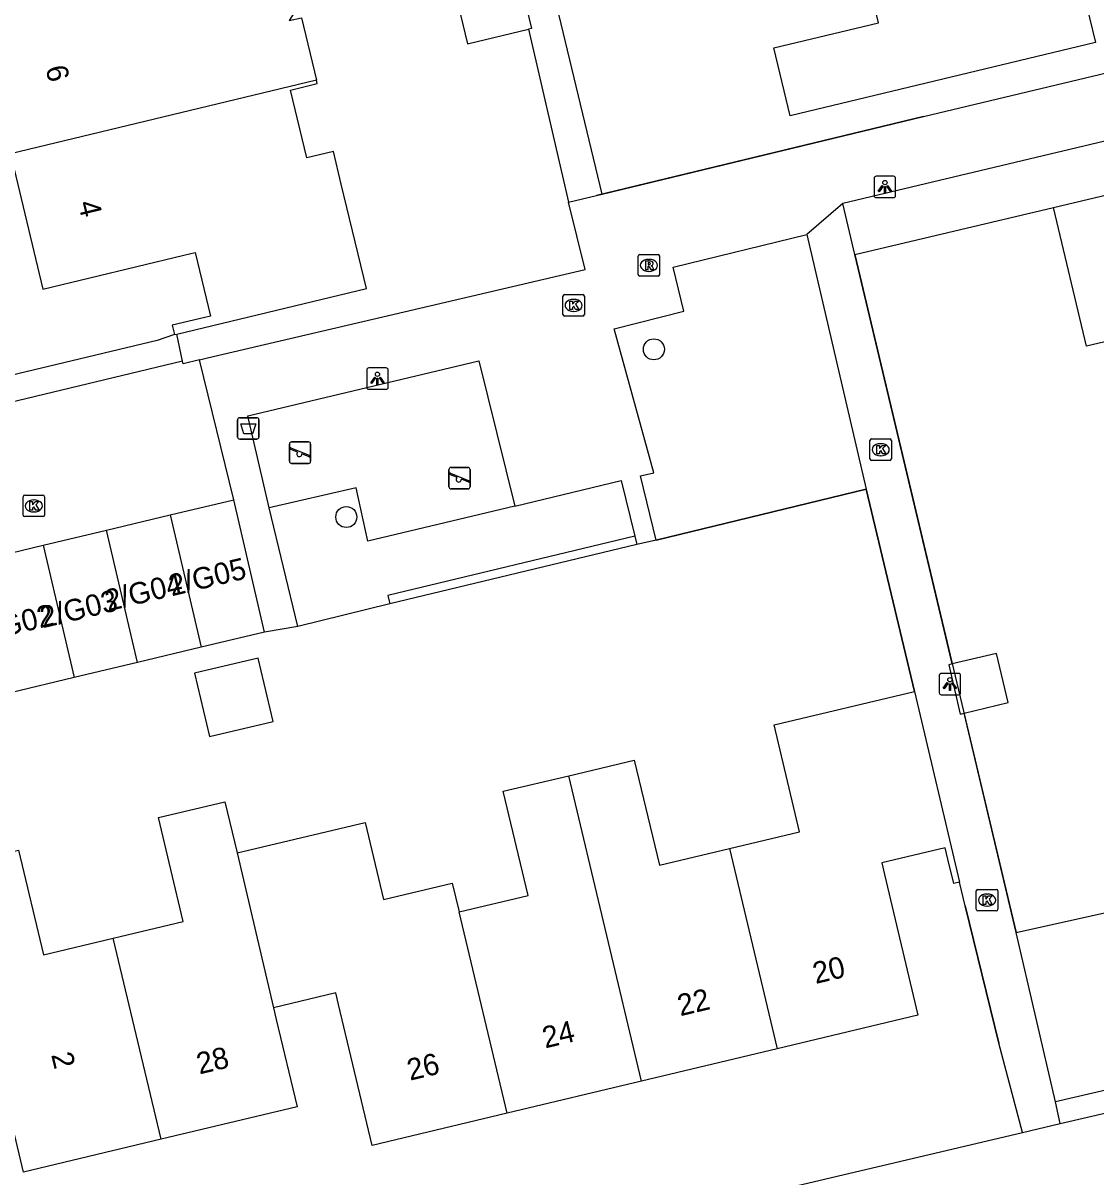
# Model space of a CAD drawing. Extents: x 157663 to 158496, y 379212 to 380934.
# Drawn here: x 158176.8 to 158226.7, y 380778.9 to 380832.6 of the extents above; entities that cross this region are included whole.
import ezdxf

# ---------------------------------------------------------------- set-up
doc = ezdxf.new("R2010")
doc.units = 0
for name, color, linetype in [('IMGEO_Afvalbak', 7, 'Continuous'), ('IMGEO_Boom', 7, 'Continuous'), ('IMGEO_Groenvoorziening', 7, 'Continuous'), ('IMGEO_Haag', 7, 'Continuous'), ('IMGEO_Hek', 7, 'Continuous'), ('IMGEO_Kolk', 7, 'Continuous'), ('IMGEO_Lichtpunt', 7, 'Continuous'), ('IMGEO_Pand', 7, 'Continuous'), ('IMGEO_Pand_nummerreeks', 7, 'Continuous'), ('IMGEO_Rijbaan_lokaal_open', 7, 'Continuous'), ('IMGEO_Rioolput', 7, 'Continuous'), ('IMGEO_Speelvoorziening', 7, 'Continuous'), ('IMGEO_Voetpad_open', 7, 'Continuous')]:
    doc.layers.add(name, color=color, linetype=linetype)

msp = doc.modelspace()

# ---------------------------------------------------------------- linework, layer by layer
at = {"layer": 'IMGEO_Afvalbak'}
for p, q in [((158186.742, 380813.303), (158186.742, 380814.103)), ((158186.742, 380814.103), (158186.742, 380813.303)), ((158186.842, 380814.203), (158187.632, 380814.203)), ((158187.632, 380814.203), (158186.842, 380814.203)), ((158187.732, 380814.103), (158187.732, 380813.303)), ((158187.732, 380813.303), (158187.732, 380814.103)), ((158187.632, 380813.203), (158186.842, 380813.203)), ((158186.842, 380813.203), (158187.632, 380813.203))]:
    msp.add_line(p, q, dxfattribs=at)
msp.add_lwpolyline([(158186.885, 380813.917), (158187.589, 380813.917), (158187.44, 380813.447), (158187.034, 380813.447), (158186.885, 380813.917)], dxfattribs=at)
for centre, start, end in [((158186.842, 380814.103), 90, 180), ((158186.842, 380814.103), 90, 180), ((158187.632, 380814.103), 0, 90), ((158187.632, 380814.103), 360, 90), ((158186.842, 380813.303), 180, 270), ((158186.842, 380813.303), 180, 270), ((158187.632, 380813.303), 270, 0), ((158187.632, 380813.303), 270, 0)]:
    msp.add_arc(centre, 0.1, start, end, dxfattribs=at)
at = {"layer": 'IMGEO_Boom'}
for centre in [(158206.111, 380817.384), (158191.799, 380809.579)]:
    msp.add_circle(centre, 0.489, dxfattribs=at)
at = {"layer": 'IMGEO_Groenvoorziening'}
for points in [[(158199.64, 380810.083), (158192.801, 380808.454), (158192.253, 380810.936), (158188.21, 380810.007)], [(158215.996, 380810.883), (158206.225, 380808.502)], [(158193.832, 380805.542), (158189.539, 380804.491)]]:
    msp.add_lwpolyline(points, dxfattribs=at)
at = {"layer": 'IMGEO_Haag'}
for points in [[(158205.233, 380808.682), (158193.739, 380805.931), (158193.832, 380805.542)], [(158205.326, 380808.293), (158193.832, 380805.542)]]:
    msp.add_lwpolyline(points, dxfattribs=at)
at = {"layer": 'IMGEO_Hek'}
for points in [[(158218.664, 380828.221), (158203.449, 380824.546)], [(158185.335, 380816.982), (158202.908, 380821.094), (158202.136, 380824.23)], [(158215.467, 380821.796), (158224.705, 380823.985)], [(158215.467, 380821.796), (158222.973, 380790.246)], [(158206.225, 380808.502), (158215.996, 380810.883)], [(158215.996, 380810.883), (158218.24, 380801.457)], [(158220.598, 380791.484), (158222.164, 380785.085)]]:
    msp.add_lwpolyline(points, dxfattribs=at)
at = {"layer": 'IMGEO_Kolk'}
for p, q in [((158201.951, 380819.93), (158202.803, 380819.93)), ((158201.876, 380819.004), (158201.876, 380819.856)), ((158202.364, 380819.71), (158202.389, 380819.71)), ((158202.877, 380819.856), (158202.877, 380819.004)), ((158202.803, 380818.93), (158201.951, 380818.93)), ((158202.387, 380819.15), (158202.362, 380819.15)), ((158216.166, 380812.287), (158216.166, 380813.139)), ((158216.241, 380813.213), (158217.093, 380813.213)), ((158216.654, 380812.993), (158216.679, 380812.993)), ((158217.167, 380813.139), (158217.167, 380812.287)), ((158216.677, 380812.433), (158216.652, 380812.433)), ((158217.093, 380812.213), (158216.241, 380812.213)), ((158176.758, 380809.67), (158176.758, 380810.522)), ((158176.833, 380810.596), (158177.685, 380810.596)), ((158177.246, 380810.376), (158177.271, 380810.376)), ((158177.759, 380810.522), (158177.759, 380809.67)), ((158177.269, 380809.816), (158177.244, 380809.816)), ((158177.685, 380809.596), (158176.833, 380809.596)), ((158221.116, 380791.324), (158221.116, 380792.176)), ((158221.191, 380792.25), (158222.043, 380792.25)), ((158221.604, 380792.03), (158221.629, 380792.03)), ((158222.117, 380792.176), (158222.117, 380791.324)), ((158221.627, 380791.47), (158221.602, 380791.47)), ((158222.043, 380791.25), (158221.191, 380791.25))]:
    msp.add_line(p, q, dxfattribs=at)
for points in [[(158201.951, 380819.93), (158202.803, 380819.93)], [(158201.876, 380819.004), (158201.876, 380819.856)], [(158202.197, 380819.63), (158202.32, 380819.63), (158202.32, 380819.479), (158202.45, 380819.63), (158202.614, 380819.63), (158202.468, 380819.479), (158202.621, 380819.23), (158202.469, 380819.23), (158202.384, 380819.394), (158202.32, 380819.327), (158202.32, 380819.23), (158202.197, 380819.23), (158202.197, 380819.63)], [(158202.877, 380819.856), (158202.877, 380819.004)], [(158202.803, 380818.93), (158201.951, 380818.93)], [(158216.166, 380812.287), (158216.166, 380813.139)], [(158216.241, 380813.213), (158217.093, 380813.213)], [(158217.167, 380813.139), (158217.167, 380812.287)], [(158216.487, 380812.913), (158216.61, 380812.913), (158216.61, 380812.762), (158216.74, 380812.913), (158216.904, 380812.913), (158216.758, 380812.762), (158216.911, 380812.513), (158216.759, 380812.513), (158216.674, 380812.677), (158216.61, 380812.61), (158216.61, 380812.513), (158216.487, 380812.513), (158216.487, 380812.913)], [(158217.093, 380812.213), (158216.241, 380812.213)], [(158176.758, 380809.67), (158176.758, 380810.522)], [(158176.833, 380810.596), (158177.685, 380810.596)], [(158177.079, 380810.296), (158177.202, 380810.296), (158177.202, 380810.145), (158177.332, 380810.296), (158177.496, 380810.296), (158177.35, 380810.145), (158177.503, 380809.896), (158177.351, 380809.896), (158177.266, 380810.06), (158177.202, 380809.993), (158177.202, 380809.896), (158177.079, 380809.896), (158177.079, 380810.296)], [(158177.759, 380810.522), (158177.759, 380809.67)], [(158177.685, 380809.596), (158176.833, 380809.596)], [(158221.116, 380791.324), (158221.116, 380792.176)], [(158221.191, 380792.25), (158222.043, 380792.25)], [(158222.117, 380792.176), (158222.117, 380791.324)], [(158221.437, 380791.95), (158221.56, 380791.95), (158221.56, 380791.799), (158221.69, 380791.95), (158221.854, 380791.95), (158221.708, 380791.799), (158221.861, 380791.55), (158221.709, 380791.55), (158221.624, 380791.714), (158221.56, 380791.647), (158221.56, 380791.55), (158221.437, 380791.55), (158221.437, 380791.95)], [(158222.043, 380791.25), (158221.191, 380791.25)]]:
    msp.add_lwpolyline(points, dxfattribs=at)
for centre, start, end in [((158201.953, 380819.854), 91.552, 178.448), ((158201.953, 380819.854), 91.552, 178.448), ((158202.801, 380819.854), 1.552, 88.448), ((158202.801, 380819.854), 1.552, 88.448), ((158201.953, 380819.006), 181.552, 268.448), ((158201.953, 380819.006), 181.552, 268.448), ((158202.801, 380819.006), 271.552, 358.448), ((158202.801, 380819.006), 271.552, 358.448), ((158216.243, 380813.137), 91.552, 178.448), ((158216.243, 380813.137), 91.552, 178.448), ((158217.091, 380813.137), 1.552, 88.448), ((158217.091, 380813.137), 1.552, 88.448), ((158216.243, 380812.289), 181.552, 268.448), ((158216.243, 380812.289), 181.552, 268.448), ((158217.091, 380812.289), 271.552, 358.448), ((158217.091, 380812.289), 271.552, 358.448), ((158176.835, 380810.52), 91.552, 178.448), ((158176.835, 380810.52), 91.552, 178.448), ((158177.683, 380810.52), 1.552, 88.448), ((158177.683, 380810.52), 1.552, 88.448), ((158176.835, 380809.672), 181.552, 268.448), ((158176.835, 380809.672), 181.552, 268.448), ((158177.683, 380809.672), 271.552, 358.448), ((158177.683, 380809.672), 271.552, 358.448), ((158221.193, 380792.174), 91.552, 178.448), ((158221.193, 380792.174), 91.552, 178.448), ((158222.041, 380792.174), 1.552, 88.448), ((158222.041, 380792.174), 1.552, 88.448), ((158221.193, 380791.326), 181.552, 268.448), ((158221.193, 380791.326), 181.552, 268.448), ((158222.041, 380791.326), 271.552, 358.448), ((158222.041, 380791.326), 271.552, 358.448)]:
    msp.add_arc(centre, 0.0765, start, end, dxfattribs=at)
for centre, major_axis, ratio, start_param, end_param in [((158202.363, 380819.43), (-0.387, 0.002), 0.722429, 4.712389, 7.853982), ((158202.388, 380819.43), (-0.39, 0.002), 0.717154, 1.570796, 4.712389), ((158216.653, 380812.713), (-0.387, 0.002), 0.722429, 4.712389, 7.853982), ((158216.678, 380812.713), (-0.39, 0.002), 0.717154, 1.570796, 4.712389), ((158177.245, 380810.096), (-0.387, 0.002), 0.722429, 4.712389, 7.853982), ((158177.27, 380810.096), (-0.39, 0.002), 0.717154, 1.570796, 4.712389), ((158221.603, 380791.75), (-0.387, 0.002), 0.722429, 4.712389, 7.853982), ((158221.628, 380791.75), (-0.39, 0.002), 0.717154, 1.570796, 4.712389)]:
    msp.add_ellipse(centre, major_axis=major_axis, ratio=ratio, start_param=start_param, end_param=end_param, dxfattribs=at)
at = {"layer": 'IMGEO_Lichtpunt'}
for p, q in [((158216.363, 380825.344), (158216.363, 380824.537)), ((158216.363, 380825.344), (158216.363, 380824.537)), ((158217.265, 380825.439), (158216.457, 380825.439)), ((158217.265, 380825.439), (158216.457, 380825.439)), ((158217.359, 380824.537), (158217.359, 380825.344)), ((158217.359, 380824.537), (158217.359, 380825.344)), ((158216.457, 380824.443), (158217.265, 380824.443)), ((158216.457, 380824.443), (158217.265, 380824.443)), ((158192.751, 380816.424), (158192.751, 380815.617)), ((158192.751, 380816.424), (158192.751, 380815.617)), ((158193.653, 380816.519), (158192.845, 380816.519)), ((158193.653, 380816.519), (158192.845, 380816.519)), ((158193.747, 380815.617), (158193.747, 380816.424)), ((158193.747, 380815.617), (158193.747, 380816.424)), ((158192.845, 380815.523), (158193.653, 380815.523)), ((158192.845, 380815.523), (158193.653, 380815.523)), ((158219.39, 380802.206), (158219.39, 380801.399)), ((158219.39, 380802.206), (158219.39, 380801.399)), ((158220.292, 380802.301), (158219.484, 380802.301)), ((158220.292, 380802.301), (158219.484, 380802.301)), ((158220.386, 380801.399), (158220.386, 380802.206)), ((158220.386, 380801.399), (158220.386, 380802.206)), ((158219.484, 380801.305), (158220.292, 380801.305)), ((158219.484, 380801.305), (158220.292, 380801.305))]:
    msp.add_line(p, q, dxfattribs=at)
for points in [[(158216.737, 380825.008), (158216.776, 380824.98), (158216.588, 380824.718), (158216.55, 380824.745), (158216.737, 380825.008)], [(158216.839, 380824.96), (158216.886, 380824.96), (158216.886, 380824.638), (158216.839, 380824.638), (158216.839, 380824.96)], [(158216.949, 380824.98), (158216.987, 380825.007), (158217.174, 380824.745), (158217.135, 380824.717), (158216.949, 380824.98)], [(158193.125, 380816.088), (158193.164, 380816.06), (158192.976, 380815.798), (158192.938, 380815.825), (158193.125, 380816.088)], [(158193.227, 380816.04), (158193.274, 380816.04), (158193.274, 380815.718), (158193.227, 380815.718), (158193.227, 380816.04)], [(158193.337, 380816.06), (158193.375, 380816.087), (158193.562, 380815.825), (158193.523, 380815.797), (158193.337, 380816.06)], [(158219.764, 380801.87), (158219.803, 380801.842), (158219.615, 380801.58), (158219.577, 380801.607), (158219.764, 380801.87)], [(158219.866, 380801.822), (158219.913, 380801.822), (158219.913, 380801.5), (158219.866, 380801.5), (158219.866, 380801.822)], [(158219.976, 380801.842), (158220.014, 380801.869), (158220.201, 380801.607), (158220.162, 380801.579), (158219.976, 380801.842)]]:
    msp.add_lwpolyline(points, dxfattribs=at)
for centre in [(158216.862, 380825.142), (158193.25, 380816.222), (158219.889, 380802.004)]:
    msp.add_circle(centre, 0.0994, dxfattribs=at)
for centre, start, end in [((158216.457, 380825.344), 90, 180), ((158216.457, 380825.344), 90, 180), ((158217.265, 380825.344), 0, 90), ((158217.265, 380825.344), 0, 90), ((158216.457, 380824.537), 180, 270), ((158216.457, 380824.537), 180, 270), ((158217.265, 380824.537), 270, 0), ((158217.265, 380824.537), 270, 360), ((158192.845, 380816.424), 90, 180), ((158192.845, 380816.424), 90, 180), ((158193.653, 380816.424), 0, 90), ((158193.653, 380816.424), 0, 90), ((158192.845, 380815.617), 180, 270), ((158192.845, 380815.617), 180, 270), ((158193.653, 380815.617), 270, 0), ((158193.653, 380815.617), 270, 360), ((158219.484, 380802.206), 90, 180), ((158219.484, 380802.206), 90, 180), ((158220.292, 380802.206), 0, 90), ((158220.292, 380802.206), 0, 90), ((158219.484, 380801.399), 180, 270), ((158219.484, 380801.399), 180, 270), ((158220.292, 380801.399), 270, 0), ((158220.292, 380801.399), 270, 360)]:
    msp.add_arc(centre, 0.0946, start, end, dxfattribs=at)
at = {"layer": 'IMGEO_Pand'}
for points in [[(158225.133, 380837.995), (158226.656, 380831.668), (158212.46, 380828.251), (158211.699, 380831.412), (158216.569, 380832.584), (158215.807, 380835.751)], [(158188.036, 380835.984), (158188.413, 380836.075), (158189.097, 380835.508), (158189.598, 380833.422), (158189.146, 380832.681), (158189.713, 380832.817), (158190.414, 380829.903)], [(158199.785, 380834.427), (158196.931, 380833.741), (158197.446, 380831.601), (158200.28, 380832.282)], [(158199.785, 380834.427), (158199.901, 380834.455), (158200.415, 380832.315), (158200.28, 380832.282)], [(158190.414, 380829.903), (158176.167, 380826.479)], [(158183.914, 380818.094), (158192.733, 380820.216), (158191.563, 380825.078), (158191.199, 380826.588), (158189.958, 380826.289), (158189.197, 380829.449), (158190.451, 380829.751), (158190.414, 380829.903)], [(158176.167, 380826.479), (158177.681, 380820.189), (158184.235, 380821.766), (158184.76, 380821.892), (158185.474, 380818.927), (158184.949, 380818.801), (158183.703, 380818.502), (158183.807, 380818.068)], [(158231.88, 380815.465), (158231.113, 380818.684), (158226.246, 380817.523), (158224.705, 380823.985), (158233.638, 380826.115), (158233.699, 380825.858), (158232.394, 380825.547), (158231.869, 380825.422), (158232.576, 380822.455), (158233.101, 380822.58), (158239.657, 380824.143), (158241.197, 380817.685)], [(158183.807, 380818.068), (158183.914, 380818.094)], [(158183.604, 380809.678), (158186.561, 380810.383)], [(158188, 380804.222), (158186.561, 380810.383)], [(158180.647, 380808.973), (158183.604, 380809.678)], [(158183.604, 380809.678), (158185.043, 380803.516)], [(158177.69, 380808.267), (158180.647, 380808.973)], [(158182.086, 380802.809), (158180.647, 380808.973)], [(158174.732, 380807.562), (158177.69, 380808.267)], [(158177.69, 380808.267), (158179.129, 380802.103)], [(158188, 380804.222), (158185.043, 380803.516)], [(158185.043, 380803.516), (158182.086, 380802.809)], [(158182.086, 380802.809), (158179.129, 380802.103)], [(158184.736, 380802.306), (158185.439, 380799.358), (158188.394, 380800.062), (158187.691, 380803.01), (158184.736, 380802.306)], [(158219.999, 380802.746), (158219.83, 380802.706), (158220.372, 380800.411), (158220.545, 380800.452)], [(158220.545, 380800.452), (158222.605, 380800.939), (158222.062, 380803.233), (158219.999, 380802.746)], [(158179.129, 380802.103), (158176.172, 380801.397)], [(158209.628, 380794.154), (158212.892, 380794.932), (158211.705, 380799.912), (158218.24, 380801.457)], [(158218.24, 380801.457), (158220.337, 380792.586)], [(158202.152, 380797.539), (158205.2, 380798.266), (158206.366, 380793.376), (158209.628, 380794.154)], [(158197.052, 380791.204), (158200.261, 380791.969), (158199.106, 380796.813), (158202.152, 380797.539)], [(158205.541, 380783.322), (158202.152, 380797.539)], [(158180.958, 380789.979), (158184.206, 380790.753), (158183.053, 380795.587), (158186.154, 380796.326), (158186.721, 380793.946)], [(158186.721, 380793.946), (158192.671, 380795.365), (158193.526, 380791.778), (158196.733, 380792.543), (158197.052, 380791.204)], [(158243.944, 380795.133), (158245.464, 380788.76), (158236.133, 380786.535), (158235.341, 380789.856), (158227.813, 380788.061), (158228.946, 380783.316), (158224.797, 380782.357)], [(158209.628, 380794.154), (158211.851, 380784.827)], [(158220.337, 380792.586), (158220.064, 380792.521), (158219.797, 380793.651), (158219.673, 380794.176), (158216.722, 380793.479), (158216.848, 380792.948), (158218.399, 380786.387), (158211.851, 380784.827)], [(158183.19, 380780.619), (158176.775, 380779.089), (158174.184, 380789.956), (158173.382, 380793.32), (158176.549, 380794.075), (158177.71, 380789.204), (158180.958, 380789.979)], [(158186.721, 380793.946), (158188.408, 380786.734)], [(158222.973, 380790.246), (158229.727, 380791.753)], [(158199.286, 380781.831), (158197.052, 380791.204)], [(158183.19, 380780.619), (158180.958, 380789.979)], [(158224.797, 380782.357), (158222.973, 380790.246)], [(158199.286, 380781.831), (158193.006, 380780.334), (158191.443, 380786.891), (158191.315, 380787.427), (158188.408, 380786.734)], [(158188.408, 380786.734), (158188.536, 380786.198), (158189.507, 380782.125), (158183.19, 380780.619)], [(158211.851, 380784.827), (158205.541, 380783.322)], [(158205.541, 380783.322), (158199.286, 380781.831)]]:
    msp.add_lwpolyline(points, dxfattribs=at)
at = {"layer": 'IMGEO_Rijbaan_lokaal_open'}
for points in [[(158184.171, 380816.835), (158172.086, 380813.928), (158165.282, 380812.425)], [(158184.967, 380816.894), (158184.209, 380816.713), (158184.171, 380816.835)], [(158186.561, 380810.383), (158184.967, 380816.894)]]:
    msp.add_lwpolyline(points, dxfattribs=at)
at = {"layer": 'IMGEO_Rioolput'}
for p, q in [((158205.38, 380820.866), (158205.38, 380821.718)), ((158205.455, 380821.792), (158206.307, 380821.792)), ((158205.868, 380821.572), (158205.893, 380821.572)), ((158206.381, 380821.718), (158206.381, 380820.866)), ((158205.891, 380821.012), (158205.866, 380821.012)), ((158206.307, 380820.792), (158205.455, 380820.792))]:
    msp.add_line(p, q, dxfattribs=at)
for points in [[(158205.38, 380820.866), (158205.38, 380821.718)], [(158205.455, 380821.792), (158206.307, 380821.792)], [(158206.381, 380821.718), (158206.381, 380820.866)], [(158205.969, 380821.49), (158205.717, 380821.492), (158205.717, 380821.092)], [(158205.717, 380821.092), (158205.841, 380821.092), (158205.841, 380821.254), (158205.852, 380821.254)], [(158205.895, 380821.411), (158205.841, 380821.411), (158205.841, 380821.33)], [(158205.841, 380821.33), (158205.893, 380821.33)], [(158205.899, 380821.225), (158205.97, 380821.092), (158206.11, 380821.092), (158206.045, 380821.218)], [(158206.307, 380820.792), (158205.455, 380820.792)]]:
    msp.add_lwpolyline(points, dxfattribs=at)
for centre, radius, start, end in [((158205.457, 380821.716), 0.0765, 91.552, 178.448), ((158205.457, 380821.716), 0.0765, 91.552, 178.448), ((158206.305, 380821.716), 0.0765, 1.552, 88.448), ((158206.305, 380821.716), 0.0765, 1.552, 88.448), ((158205.851, 380821.201), 0.0533, 26.0293, 88.6989), ((158205.877, 380821.519), 0.19, 274.7715, 282.9687), ((158205.901, 380821.315), 0.0964, 77.0061, 93.1865), ((158205.915, 380821.372), 0.0378, 276.6634, 79.6772), ((158205.968, 380821.38), 0.109, 350.3612, 89.416), ((158205.966, 380821.38), 0.112, 277.5842, 350.9817), ((158205.95, 380821.165), 0.108, 29.5134, 73.7905), ((158205.457, 380820.868), 0.0765, 181.552, 268.448), ((158205.457, 380820.868), 0.0765, 181.552, 268.448), ((158206.305, 380820.868), 0.0765, 271.552, 358.448), ((158206.305, 380820.868), 0.0765, 271.552, 358.448)]:
    msp.add_arc(centre, radius, start, end, dxfattribs=at)
for centre, major_axis, ratio, start_param, end_param in [((158205.867, 380821.292), (-0.387, 0.002), 0.722429, 4.712389, 7.853982), ((158205.892, 380821.292), (-0.39, 0.002), 0.717154, 1.570796, 4.712389)]:
    msp.add_ellipse(centre, major_axis=major_axis, ratio=ratio, start_param=start_param, end_param=end_param, dxfattribs=at)
at = {"layer": 'IMGEO_Speelvoorziening'}
for p, q in [((158189.15, 380812.172), (158189.15, 380812.972)), ((158189.15, 380812.972), (158189.15, 380812.172)), ((158189.25, 380813.072), (158190.04, 380813.072)), ((158190.04, 380813.072), (158189.25, 380813.072)), ((158190.14, 380812.972), (158190.14, 380812.172)), ((158190.14, 380812.172), (158190.14, 380812.972)), ((158189.533, 380812.6), (158189.194, 380812.737)), ((158189.219, 380812.797), (158190.095, 380812.444)), ((158190.071, 380812.384), (158189.731, 380812.521)), ((158190.04, 380812.072), (158189.25, 380812.072)), ((158189.25, 380812.072), (158190.04, 380812.072)), ((158196.673, 380811.889), (158197.463, 380811.889)), ((158197.463, 380811.889), (158196.673, 380811.889)), ((158196.573, 380810.989), (158196.573, 380811.789)), ((158196.573, 380811.789), (158196.573, 380810.989)), ((158196.956, 380811.417), (158196.617, 380811.554)), ((158196.642, 380811.614), (158197.518, 380811.261)), ((158197.494, 380811.201), (158197.154, 380811.338)), ((158197.563, 380811.789), (158197.563, 380810.989)), ((158197.563, 380810.989), (158197.563, 380811.789)), ((158197.463, 380810.889), (158196.673, 380810.889)), ((158196.673, 380810.889), (158197.463, 380810.889))]:
    msp.add_line(p, q, dxfattribs=at)
for centre, radius, start, end in [((158189.25, 380812.972), 0.1, 90, 180), ((158189.25, 380812.972), 0.1, 90, 180), ((158190.04, 380812.972), 0.1, 0, 90), ((158190.04, 380812.972), 0.1, 360, 90), ((158189.207, 380812.767), 0.0327, 68.078, 248.078), ((158189.612, 380812.51), 0.12, 130.9928, 5.1632), ((158190.083, 380812.414), 0.0327, 248.078, 68.078), ((158189.25, 380812.172), 0.1, 180, 270), ((158189.25, 380812.172), 0.1, 180, 270), ((158190.04, 380812.172), 0.1, 270, 0), ((158190.04, 380812.172), 0.1, 270, 0), ((158196.673, 380811.789), 0.1, 90, 180), ((158196.673, 380811.789), 0.1, 90, 180), ((158197.463, 380811.789), 0.1, 0, 90), ((158197.463, 380811.789), 0.1, 360, 90), ((158196.63, 380811.584), 0.0327, 68.078, 248.078), ((158197.035, 380811.327), 0.12, 130.9928, 5.1632), ((158196.673, 380810.989), 0.1, 180, 270), ((158196.673, 380810.989), 0.1, 180, 270), ((158197.463, 380810.989), 0.1, 270, 0), ((158197.463, 380810.989), 0.1, 270, 0), ((158197.506, 380811.231), 0.0327, 248.078, 68.078)]:
    msp.add_arc(centre, radius, start, end, dxfattribs=at)
at = {"layer": 'IMGEO_Voetpad_open'}
for points in [[(158183.807, 380818.068), (158182.999, 380817.796), (158172.223, 380815.219), (158171.793, 380815.099), (158170.989, 380818.524), (158169.526, 380824.707), (158165.739, 380840.623), (158168.671, 380841.291), (158163.827, 380862.151)], [(158203.704, 380824.608), (158200.29, 380838.795), (158205.081, 380839.948), (158202.47, 380851.277)], [(158200.28, 380832.282), (158202.136, 380824.23)], [(158203.704, 380824.608), (158218.664, 380828.221), (158227.569, 380830.344), (158234.881, 380832.061)], [(158245.325, 380828.86), (158243.553, 380828.469), (158243.032, 380830.777), (158234.097, 380828.753), (158232.966, 380828.488), (158230.614, 380827.909), (158214.903, 380824.164)], [(158184.967, 380816.894), (158185.335, 380816.982), (158202.908, 380821.094), (158202.136, 380824.23)], [(158202.136, 380824.23), (158203.449, 380824.546), (158203.704, 380824.608)], [(158214.903, 380824.164), (158213.234, 380822.726)], [(158219.999, 380802.746), (158215.467, 380821.796), (158214.903, 380824.164)], [(158206.225, 380808.502), (158205.49, 380811.494), (158206.107, 380811.638), (158204.271, 380818.337), (158207.513, 380819.159), (158207.011, 380821.205), (158213.234, 380822.726)], [(158213.234, 380822.726), (158215.996, 380810.883)], [(158184.171, 380816.835), (158183.914, 380818.094)], [(158188.21, 380810.007), (158187.219, 380814.29), (158197.961, 380816.843), (158199.64, 380810.083)], [(158199.64, 380810.083), (158204.589, 380811.276), (158205.233, 380808.682)], [(158218.24, 380801.457), (158215.996, 380810.883)], [(158189.539, 380804.491), (158188.21, 380810.007)], [(158205.233, 380808.682), (158205.326, 380808.293)], [(158206.225, 380808.502), (158205.326, 380808.293)], [(158189.539, 380804.491), (158188, 380804.222)], [(158222.973, 380790.246), (158220.545, 380800.452)], [(158223.26, 380780.934), (158222.164, 380785.085), (158220.598, 380791.484), (158220.337, 380792.586)], [(158225.024, 380781.358), (158229.504, 380782.395), (158241.023, 380785.136), (158254.914, 380788.414)], [(158225.024, 380781.358), (158224.797, 380782.357)], [(158223.26, 380780.934), (158225.024, 380781.358)], [(158176.43, 380774.313), (158177.439, 380770.137), (158223.26, 380780.934)]]:
    msp.add_lwpolyline(points, dxfattribs=at)

# ---------------------------------------------------------------- texts
at = {"layer": 'IMGEO_Pand_nummerreeks'}
for s, rotation, p in [('6', 283.5331, (158177.795, 380830.481)), ('4', 283.5331, (158179.309, 380824.192)), ('2/G05', 13.4446, (158183.672, 380805.886)), ('2/G04', 13.4446, (158180.706, 380805.185)), ('2/G03', 13.4446, (158177.686, 380804.403)), ('2/G02', 13.4446, (158174.713, 380803.727)), ('20', 13.4088, (158213.64, 380787.844)), ('22', 13.4088, (158207.343, 380786.342)), ('24', 13.4088, (158201.055, 380784.844)), ('2', 283.4103, (158178.063, 380784.554)), ('28', 13.412, (158184.964, 380783.633)), ('26', 13.4072, (158194.763, 380783.343))]:
    msp.add_text(s, height=1, rotation=rotation, dxfattribs=at).set_placement(p)

doc.saveas('drawing.dxf')
